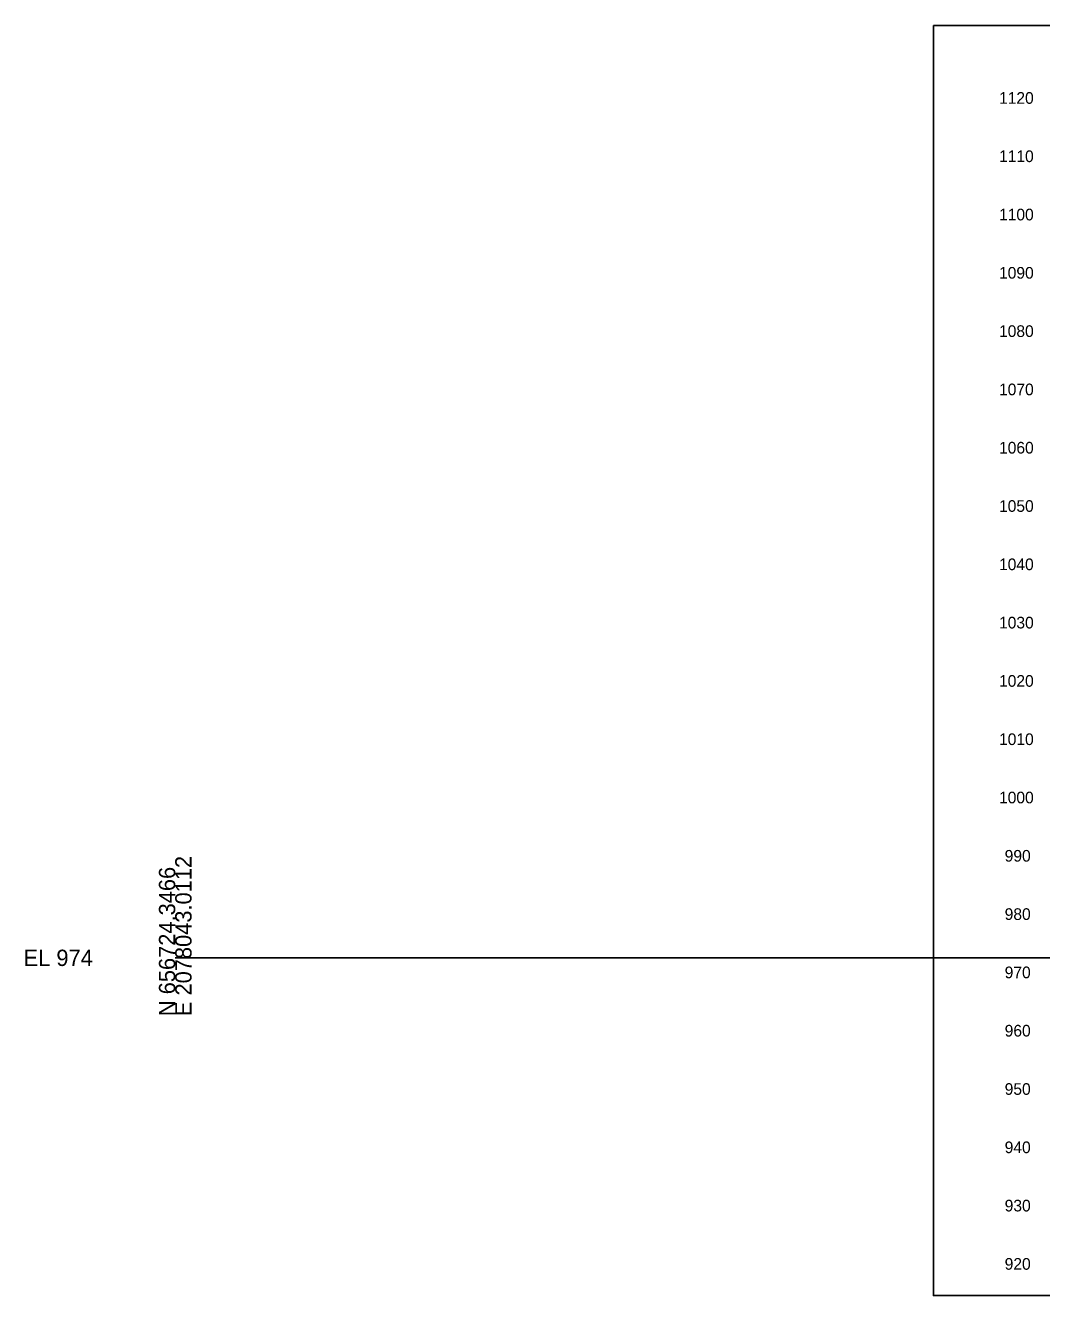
# Model space of a CAD drawing. Extents: x 5868 to 6683, y 2883 to 19120.
# Drawn here: x 5868.1 to 6042.3, y 18887.1 to 19105 of the extents above; entities that cross this region are included whole.
import ezdxf

# ---------------------------------------------------------------- set-up
doc = ezdxf.new("R2010")
doc.units = 0
for name, color, linetype in [('DESIGN - SHEET - Corner Text', 7, 'Continuous'), ('DESIGN - SHEET - Light Grid', 7, 'Continuous'), ('DESIGN - SHEET - Plot Shape', 7, 'Continuous')]:
    doc.layers.add(name, color=color, linetype=linetype)

msp = doc.modelspace()

# ---------------------------------------------------------------- linework, layer by layer
at = {"layer": 'DESIGN - SHEET - Light Grid'}
msp.add_line((5893.78, 18945.07), (6193.78, 18945.07), dxfattribs=at)
at = {"layer": 'DESIGN - SHEET - Plot Shape'}
msp.add_lwpolyline([(6023.78, 19105.01), (6363.78, 19105.01), (6363.78, 18887.13), (6023.78, 18887.13)], close=True, dxfattribs=at)
msp.add_lwpolyline([(6023.78, 19105.01), (6363.78, 19105.01), (6363.78, 18887.13), (6023.78, 18887.13)], close=True, dxfattribs=at)
msp.add_lwpolyline([(6023.78, 19105.01), (6363.78, 19105.01), (6363.78, 18887.13), (6023.78, 18887.13)], close=True, dxfattribs=at)

# ---------------------------------------------------------------- texts
at = {"layer": 'DESIGN - SHEET - Corner Text'}
for s, p in [('1120', (6035.03, 19091.57)), ('1120', (6035.03, 19091.57)), ('1120', (6035.03, 19091.57)), ('1110', (6035.03, 19081.57)), ('1110', (6035.03, 19081.57)), ('1110', (6035.03, 19081.57)), ('1100', (6035.03, 19071.57)), ('1100', (6035.03, 19071.57)), ('1100', (6035.03, 19071.57)), ('1090', (6035.03, 19061.57)), ('1090', (6035.03, 19061.57)), ('1090', (6035.03, 19061.57)), ('1080', (6035.03, 19051.57)), ('1080', (6035.03, 19051.57)), ('1080', (6035.03, 19051.57)), ('1070', (6035.03, 19041.57)), ('1070', (6035.03, 19041.57)), ('1070', (6035.03, 19041.57)), ('1060', (6035.03, 19031.57)), ('1060', (6035.03, 19031.57)), ('1060', (6035.03, 19031.57)), ('1050', (6035.03, 19021.57)), ('1050', (6035.03, 19021.57)), ('1050', (6035.03, 19021.57)), ('1040', (6035.03, 19011.57)), ('1040', (6035.03, 19011.57)), ('1040', (6035.03, 19011.57)), ('1030', (6035.03, 19001.57)), ('1030', (6035.03, 19001.57)), ('1030', (6035.03, 19001.57)), ('1020', (6035.03, 18991.57)), ('1020', (6035.03, 18991.57)), ('1020', (6035.03, 18991.57)), ('1010', (6035.03, 18981.57)), ('1010', (6035.03, 18981.57)), ('1010', (6035.03, 18981.57)), ('1000', (6035.03, 18971.57)), ('1000', (6035.03, 18971.57)), ('1000', (6035.03, 18971.57)), ('990', (6036, 18961.57)), ('990', (6036, 18961.57)), ('990', (6036, 18961.57)), ('980', (6036, 18951.57)), ('980', (6036, 18951.57)), ('980', (6036, 18951.57)), ('970', (6036, 18941.57)), ('970', (6036, 18941.57)), ('970', (6036, 18941.57)), ('960', (6036, 18931.57)), ('960', (6036, 18931.57)), ('960', (6036, 18931.57)), ('950', (6036, 18921.57)), ('950', (6036, 18921.57)), ('950', (6036, 18921.57)), ('940', (6036, 18911.57)), ('940', (6036, 18911.57)), ('940', (6036, 18911.57)), ('930', (6036, 18901.57)), ('930', (6036, 18901.57)), ('930', (6036, 18901.57)), ('920', (6036, 18891.57)), ('920', (6036, 18891.57)), ('920', (6036, 18891.57))]:
    msp.add_text(s, height=2, dxfattribs=at).set_placement(p)
at = {"layer": 'DESIGN - SHEET - Light Grid'}
for s, p in [('E 2078043.0112', (5896.58, 18935.07)), ('N 656724.3466', (5893.78, 18935.07))]:
    msp.add_text(s, height=2.8, rotation=90, dxfattribs=at).set_placement(p)
msp.add_text('EL 974', height=2.8, dxfattribs=at).set_placement((5867.78, 18943.67))

doc.saveas('drawing.dxf')
